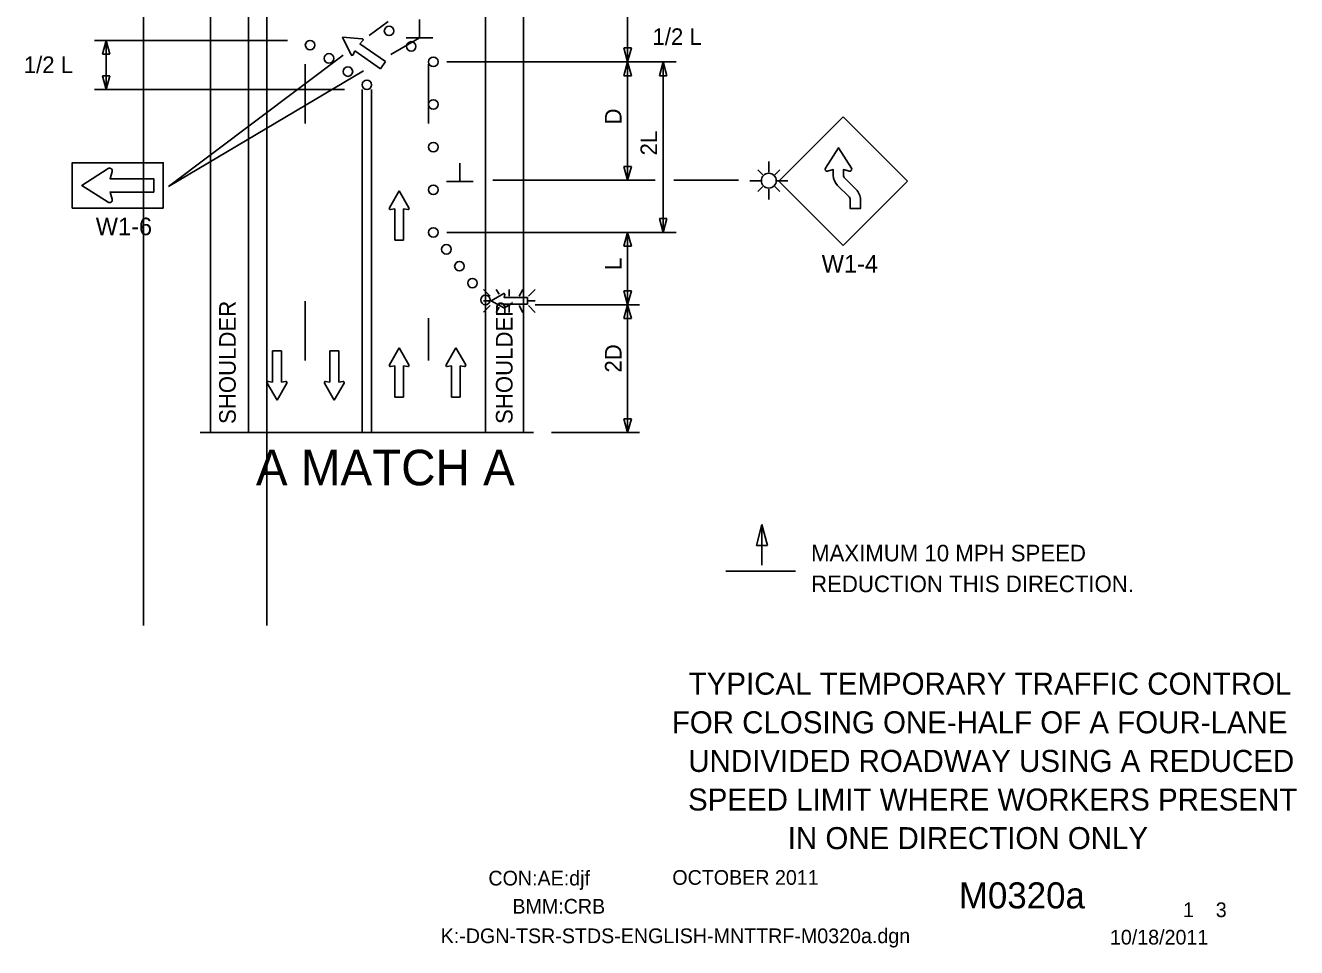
# Model space of a CAD drawing. Extents: x 16473 to 19504, y 4850 to 6923.
# Drawn here: x 16895 to 17432, y 5932 to 6321 of the extents above; entities that cross this region are included whole.
import ezdxf

# ---------------------------------------------------------------- set-up
doc = ezdxf.new("R2010")
doc.units = 0
for name, color, linetype in [('ALI_LEGAL_EX', 7, 'Continuous'), ('BORDER_SIGNAL_WO', 7, 'Continuous'), ('MT_SCRATCH_LEVEL_E', 7, 'Continuous'), ('PAVT_EDGE_EX', 7, 'Continuous'), ('TRAFFIC_SIGNS_PR', 7, 'Continuous'), ('TYPICAL_TEXT_DIMEN_PR', 7, 'Continuous')]:
    doc.layers.add(name, color=color, linetype=linetype)

msp = doc.modelspace()

# ---------------------------------------------------------------- linework, layer by layer
at = {"layer": 'ALI_LEGAL_EX'}
for p, q in [((16945.19, 6918.86), (16945.19, 6067.75)), ((16997.19, 6918.86), (16997.19, 6067.75))]:
    msp.add_line(p, q, dxfattribs=at)
for points in [[(17013.43, 6304.69), (17013.43, 6279.69)], [(17065.43, 6304.69), (17065.43, 6279.69)], [(17013.43, 6204.69), (17013.43, 6179.69)], [(17065.43, 6197.47), (17065.43, 6179.69)]]:
    msp.add_lwpolyline(points, dxfattribs=at)
at = {"layer": 'MT_SCRATCH_LEVEL_E'}
for p, q in [((17029.15, 6316.2), (17032.73, 6308.68)), ((17037.46, 6315.45), (17029.15, 6316.2)), ((17029.15, 6316.2), (17032.73, 6308.68)), ((17037.46, 6315.45), (17029.15, 6316.2)), ((17036.47, 6313.39), (17037.74, 6314.67)), ((17036.47, 6313.39), (17037.74, 6314.67)), ((17047.34, 6305.8), (17036.47, 6313.39)), ((17047.34, 6305.8), (17036.47, 6313.39)), ((17033.57, 6308.69), (17034.33, 6310.33)), ((17033.57, 6308.69), (17034.33, 6310.33)), ((17034.33, 6310.33), (17045.19, 6302.73)), ((17034.33, 6310.33), (17045.19, 6302.73)), ((17045.19, 6302.73), (17047.34, 6305.8)), ((17045.19, 6302.73), (17047.34, 6305.8)), ((17053.03, 6251.28), (17048.92, 6244.04)), ((17053.03, 6251.28), (17048.92, 6244.04)), ((17057.17, 6244.04), (17053.03, 6251.28)), ((17057.17, 6244.04), (17053.03, 6251.28)), ((17049.4, 6243.36), (17051.17, 6243.67)), ((17049.4, 6243.36), (17051.17, 6243.67)), ((17051.17, 6243.67), (17051.17, 6230.42)), ((17051.17, 6243.67), (17051.17, 6230.42)), ((17054.92, 6230.42), (17054.92, 6243.67)), ((17054.92, 6243.67), (17056.69, 6243.36)), ((17054.92, 6230.42), (17054.92, 6243.67)), ((17054.92, 6243.67), (17056.69, 6243.36)), ((17051.17, 6230.42), (17054.92, 6230.42)), ((17051.17, 6230.42), (17054.92, 6230.42)), ((17053.03, 6185.06), (17048.92, 6177.82)), ((17053.03, 6185.06), (17048.92, 6177.82)), ((17057.17, 6177.82), (17053.03, 6185.06)), ((17057.17, 6177.82), (17053.03, 6185.06)), ((17076.95, 6185.06), (17072.84, 6177.82)), ((17076.95, 6185.06), (17072.84, 6177.82)), ((17081.1, 6177.82), (17076.95, 6185.06)), ((17081.1, 6177.82), (17076.95, 6185.06)), ((17003.35, 6183.78), (16999.61, 6183.78)), ((16999.61, 6183.78), (16999.61, 6170.52)), ((17003.35, 6183.78), (16999.61, 6183.78)), ((16999.61, 6183.78), (16999.61, 6170.52)), ((17003.35, 6170.52), (17003.35, 6183.78)), ((17003.35, 6170.52), (17003.35, 6183.78)), ((17027.53, 6183.78), (17023.79, 6183.78)), ((17023.79, 6183.78), (17023.79, 6170.52)), ((17027.53, 6183.78), (17023.79, 6183.78)), ((17023.79, 6183.78), (17023.79, 6170.52)), ((17027.53, 6170.52), (17027.53, 6183.78)), ((17027.53, 6170.52), (17027.53, 6183.78)), ((17049.4, 6177.14), (17051.17, 6177.45)), ((17049.4, 6177.14), (17051.17, 6177.45)), ((17051.17, 6177.45), (17051.17, 6164.2)), ((17051.17, 6177.45), (17051.17, 6164.2)), ((17054.92, 6164.2), (17054.92, 6177.45)), ((17054.92, 6177.45), (17056.69, 6177.14)), ((17054.92, 6164.2), (17054.92, 6177.45)), ((17054.92, 6177.45), (17056.69, 6177.14)), ((17073.32, 6177.14), (17075.1, 6177.45)), ((17073.32, 6177.14), (17075.1, 6177.45)), ((17075.1, 6177.45), (17075.1, 6164.2)), ((17075.1, 6177.45), (17075.1, 6164.2)), ((17078.84, 6164.2), (17078.84, 6177.45)), ((17078.84, 6177.45), (17080.62, 6177.14)), ((17078.84, 6164.2), (17078.84, 6177.45)), ((17078.84, 6177.45), (17080.62, 6177.14)), ((16997.35, 6170.15), (17001.5, 6162.91)), ((16997.35, 6170.15), (17001.5, 6162.91)), ((16999.61, 6170.52), (16997.83, 6170.84)), ((16999.61, 6170.52), (16997.83, 6170.84)), ((17001.5, 6162.91), (17005.61, 6170.15)), ((17001.5, 6162.91), (17005.61, 6170.15)), ((17005.13, 6170.84), (17003.35, 6170.52)), ((17005.13, 6170.84), (17003.35, 6170.52)), ((17021.53, 6170.15), (17025.68, 6162.91)), ((17021.53, 6170.15), (17025.68, 6162.91)), ((17023.79, 6170.52), (17022.01, 6170.84)), ((17023.79, 6170.52), (17022.01, 6170.84)), ((17025.68, 6162.91), (17029.79, 6170.15)), ((17025.68, 6162.91), (17029.79, 6170.15)), ((17029.31, 6170.84), (17027.53, 6170.52)), ((17029.31, 6170.84), (17027.53, 6170.52)), ((17051.17, 6164.2), (17054.92, 6164.2)), ((17051.17, 6164.2), (17054.92, 6164.2)), ((17075.1, 6164.2), (17078.84, 6164.2)), ((17075.1, 6164.2), (17078.84, 6164.2))]:
    msp.add_line(p, q, dxfattribs=at)
for centre, start, end in [((17037.41, 6314.99), 315.105, 84.8419), ((17037.41, 6314.99), 315.105, 84.8419), ((17033.15, 6308.89), 205.4936, 335.0326), ((17033.15, 6308.89), 205.4936, 335.0326), ((17049.32, 6243.82), 150.4248, 279.9638), ((17049.32, 6243.82), 150.4248, 279.9638), ((17056.76, 6243.82), 260.0362, 29.7731), ((17056.76, 6243.82), 260.0362, 29.7731), ((17049.32, 6177.6), 150.4248, 279.9638), ((17049.32, 6177.6), 150.4248, 279.9638), ((17056.76, 6177.6), 260.0362, 29.7731), ((17056.76, 6177.6), 260.0362, 29.7731), ((17073.25, 6177.6), 150.4248, 279.9638), ((17073.25, 6177.6), 150.4248, 279.9638), ((17080.69, 6177.6), 260.0362, 29.7731), ((17080.69, 6177.6), 260.0362, 29.7731), ((16997.76, 6170.37), 80.0362, 209.7731), ((16997.76, 6170.37), 80.0362, 209.7731), ((17005.2, 6170.38), 330.4248, 99.9638), ((17005.2, 6170.38), 330.4248, 99.9638), ((17021.94, 6170.37), 80.0362, 209.7731), ((17021.94, 6170.37), 80.0362, 209.7731), ((17029.38, 6170.38), 330.4248, 99.9638), ((17029.38, 6170.38), 330.4248, 99.9638)]:
    msp.add_arc(centre, 0.463, start, end, dxfattribs=at)
at = {"layer": 'PAVT_EDGE_EX'}
for p, q in [((16973.43, 6873.99), (16973.43, 6149.2)), ((16989.43, 6873.99), (16989.43, 6149.2)), ((17089.43, 6873.99), (17089.43, 6149.2)), ((17105.43, 6873.99), (17105.43, 6149.2)), ((17037.43, 6294.02), (17037.43, 6149.2)), ((17041.43, 6294.02), (17041.43, 6149.2))]:
    msp.add_line(p, q, dxfattribs=at)
at = {"layer": 'TRAFFIC_SIGNS_PR'}
for p, q in [((17213.17, 6255.35), (17240.32, 6282.5)), ((17267.47, 6255.35), (17240.32, 6282.5)), ((16930.24, 6260.66), (16919.08, 6253.56)), ((16931.08, 6256.36), (16931.92, 6259.42)), ((17206.49, 6258.07), (17204.38, 6260.18)), ((17209, 6259.11), (17209, 6263.61)), ((17211.51, 6258.07), (17213.62, 6260.18)), ((16949.48, 6256.36), (16931.08, 6256.36)), ((16949.48, 6256.36), (16949.48, 6250.76)), ((17205.84, 6255.56), (17201.01, 6255.56)), ((17212.15, 6255.56), (17217.03, 6255.56)), ((17240.32, 6228.2), (17213.17, 6255.35)), ((17267.47, 6255.35), (17240.32, 6228.2)), ((17245.79, 6251.88), (17241.08, 6256.6)), ((17241.08, 6256.6), (17245.79, 6251.88)), ((16919.08, 6253.56), (16930.24, 6246.46)), ((16931.92, 6247.7), (16931.08, 6250.76)), ((16931.08, 6250.76), (16949.48, 6250.76)), ((17206.48, 6253.04), (17204.38, 6250.94)), ((17209, 6247.59), (17209, 6252)), ((17211.51, 6253.04), (17213.62, 6250.94)), ((17242.74, 6248.83), (17238.03, 6253.55)), ((17242.74, 6248.83), (17238.03, 6253.55)), ((17088.56, 6209.69), (17091.38, 6206.87)), ((17094, 6209.69), (17095.21, 6207.59)), ((17099.47, 6206.87), (17099.47, 6209.69)), ((17105.26, 6209.69), (17103.63, 6206.87)), ((17107.55, 6206.87), (17110.37, 6209.69)), ((17091.38, 6204.84), (17088.56, 6204.84)), ((17088.56, 6199.99), (17091.38, 6202.8)), ((17095.28, 6202.17), (17094.02, 6199.98)), ((17099.47, 6202.8), (17099.47, 6199.98)), ((17103.6, 6202.8), (17105.23, 6199.98)), ((17107.55, 6204.84), (17110.37, 6204.84)), ((17107.55, 6202.8), (17110.37, 6199.98))]:
    msp.add_line(p, q, dxfattribs=at)
for points in [[(17232.87, 6260.87), (17238.36, 6269.48), (17243.84, 6260.87)], [(17232.87, 6260.87), (17238.36, 6269.48), (17243.84, 6260.87)], [(16930.24, 6246.46), (16919.08, 6253.56), (16930.24, 6260.66)], [(16931.92, 6259.42), (16931.08, 6256.36), (16949.48, 6256.36), (16949.48, 6250.76), (16931.08, 6250.76), (16931.92, 6247.7)], [(17236.2, 6257.86), (17236.2, 6260.22), (17233.83, 6259.58)], [(17236.2, 6257.86), (17236.2, 6260.22), (17233.83, 6259.58)], [(17242.88, 6259.58), (17240.51, 6260.22), (17240.52, 6257.93)], [(17242.88, 6259.57), (17242.04, 6259.8), (17240.51, 6260.22), (17240.52, 6257.93)], [(17247.66, 6247.46), (17247.66, 6243.76), (17243.34, 6243.76), (17243.34, 6247.46)], [(17097.14, 6201.82), (17091.83, 6204.84), (17097.14, 6207.88)], [(17097.64, 6207.52), (17097.41, 6206.22), (17107.13, 6206.22), (17107.13, 6203.48), (17097.41, 6203.48), (17097.64, 6202.17)]]:
    msp.add_lwpolyline(points, dxfattribs=at)
msp.add_lwpolyline([(16953.48, 6243.96), (16915.08, 6243.96), (16915.08, 6263.16), (16953.48, 6263.16)], close=True, dxfattribs=at)
for centre, radius in [((17048.77, 6318.77), 2), ((17015.43, 6312.78), 2), ((17058.11, 6312.24), 2), ((17023.43, 6307.19), 2), ((17067.46, 6305.72), 2), ((17031.43, 6301.6), 2), ((17039.43, 6296.02), 2), ((17067.46, 6287.72), 2), ((17067.46, 6269.72), 2), ((17067.46, 6251.72), 2), ((17209, 6255.56), 3.15), ((17067.46, 6233.72), 2), ((17072.95, 6226.58), 2), ((17078.45, 6219.46), 2), ((17083.95, 6212.33), 2), ((17089.44, 6205.2), 2)]:
    msp.add_circle(centre, radius, dxfattribs=at)
for centre, radius, start, end in [((16930.84, 6259.72), 1.12, 344.6731, 122.4696), ((16930.84, 6259.72), 1.12, 344.6731, 122.4696), ((17233.6, 6260.41), 0.866, 147.7292, 285.3172), ((17233.61, 6260.41), 0.866, 147.7196, 285.3201), ((17223.76, 6266.67), 10.8, 327.5335, 327.5431), ((17236.69, 6249.16), 10.8, 105.3192, 105.32), ((17243.11, 6260.41), 0.866, 254.6148, 32.4712), ((17242.37, 6257.92), 6.17, 180.6181, 225.7875), ((17242.37, 6257.93), 6.17, 180.6245, 225.2313), ((17242.37, 6257.93), 1.85, 179.8762, 225.7877), ((17242.37, 6257.92), 1.85, 180, 225.7875), ((17241.49, 6247.46), 1.85, 0, 47.628), ((17241.49, 6247.46), 6.17, 0, 45.7883), ((16930.84, 6247.4), 1.12, 237.5304, 15.3269), ((16930.84, 6247.4), 1.12, 237.5304, 15.3269), ((17097.3, 6207.58), 0.341, 350.0407, 118.5167), ((17097.31, 6202.12), 0.341, 241.1084, 9.2692)]:
    msp.add_arc(centre, radius, start, end, dxfattribs=at)
at = {"layer": 'TYPICAL_TEXT_DIMEN_PR'}
for p, q in [((17061.59, 6315.87), (17061.59, 6323.65)), ((17149.43, 6327.29), (17149.43, 6305.72)), ((17040.39, 6316.77), (17048.33, 6322.74)), ((16924.43, 6314.78), (17005.97, 6314.78)), ((16927.86, 6308.91), (16929.43, 6314.78)), ((16929.43, 6294.02), (16929.43, 6314.78)), ((16929.43, 6314.78), (16931, 6308.91)), ((17061.59, 6315.87), (17049.59, 6308.76)), ((17067.21, 6315.87), (17055.96, 6315.87)), ((16929.43, 6308.91), (16927.86, 6308.91)), ((16931, 6308.91), (16929.43, 6308.91)), ((16955.69, 6253.16), (17029.36, 6308.49)), ((17149.43, 6305.72), (17147.86, 6311.58)), ((17147.86, 6311.58), (17149.43, 6311.58)), ((17149.43, 6311.58), (17151, 6311.58)), ((17151, 6311.58), (17149.43, 6305.72)), ((17154.43, 6305.72), (17073.2, 6305.72)), ((17154.43, 6305.72), (17073.2, 6305.72)), ((17169.86, 6305.72), (17073.2, 6305.72)), ((17147.86, 6299.86), (17149.43, 6305.72)), ((17149.43, 6255.72), (17149.43, 6305.72)), ((17149.43, 6305.72), (17151, 6299.86)), ((17162.86, 6299.86), (17164.43, 6305.72)), ((17164.43, 6233.72), (17164.43, 6305.72)), ((17164.43, 6305.72), (17166, 6299.86)), ((16929.43, 6294.02), (16927.86, 6299.88)), ((16927.86, 6299.88), (16929.43, 6299.88)), ((16929.43, 6299.88), (16931, 6299.88)), ((16931, 6299.88), (16929.43, 6294.02)), ((17037.99, 6301.89), (16955.69, 6253.16)), ((17149.43, 6299.86), (17147.86, 6299.86)), ((17151, 6299.86), (17149.43, 6299.86)), ((17164.43, 6299.86), (17162.86, 6299.86)), ((17166, 6299.86), (17164.43, 6299.86)), ((16924.43, 6294.02), (17029.97, 6294.02)), ((17078.59, 6255.17), (17078.59, 6262.96)), ((17149.43, 6255.72), (17147.86, 6261.58)), ((17147.86, 6261.58), (17149.43, 6261.58)), ((17149.43, 6261.58), (17151, 6261.58)), ((17151, 6261.58), (17149.43, 6255.72)), ((17084.22, 6255.17), (17072.97, 6255.17)), ((17161.07, 6255.72), (17092.61, 6255.72)), ((17196.26, 6255.72), (17168.98, 6255.72)), ((17164.43, 6233.72), (17162.86, 6239.58)), ((17162.86, 6239.58), (17164.43, 6239.58)), ((17164.43, 6239.58), (17166, 6239.58)), ((17166, 6239.58), (17164.43, 6233.72)), ((17169.86, 6233.72), (17073.2, 6233.72)), ((17147.86, 6227.85), (17149.43, 6233.72)), ((17149.43, 6203.2), (17149.43, 6233.72)), ((17149.43, 6233.72), (17151, 6227.85)), ((17149.43, 6227.85), (17147.86, 6227.85)), ((17151, 6227.85), (17149.43, 6227.85)), ((17149.43, 6203.2), (17147.86, 6209.07)), ((17147.86, 6209.07), (17149.43, 6209.07)), ((17149.43, 6209.07), (17151, 6209.07)), ((17151, 6209.07), (17149.43, 6203.2)), ((17154.43, 6203.2), (17110.45, 6203.2)), ((17147.86, 6197.34), (17149.43, 6203.2)), ((17149.43, 6203.2), (17149.43, 6149.2)), ((17149.43, 6203.2), (17151, 6197.34)), ((17149.43, 6197.34), (17147.86, 6197.34)), ((17151, 6197.34), (17149.43, 6197.34)), ((17149.43, 6149.2), (17147.86, 6155.07)), ((17147.86, 6155.07), (17149.43, 6155.07)), ((17149.43, 6155.07), (17151, 6155.07)), ((17151, 6155.07), (17149.43, 6149.2)), ((16969.13, 6149.2), (17109.73, 6149.2)), ((17154.43, 6149.2), (17117.3, 6149.2)), ((17203.76, 6101.57), (17206.12, 6110.36)), ((17206.12, 6093.23), (17206.12, 6110.36)), ((17206.12, 6110.36), (17208.47, 6101.57)), ((17206.12, 6101.57), (17203.76, 6101.57)), ((17208.47, 6101.57), (17206.12, 6101.57)), ((17220.29, 6090.73), (17190.85, 6090.73))]:
    msp.add_line(p, q, dxfattribs=at)

# ---------------------------------------------------------------- texts
at = {"layer": 'BORDER_SIGNAL_WO'}
for s, height, p in [('TYPICAL TEMPORARY TRAFFIC CONTROL', 9.3, (17175.21, 6038.59)), ('FOR CLOSING ONE-HALF OF A FOUR-LANE', 9.3, (17168.06, 6022.29)), ('UNDIVIDED ROADWAY USING A REDUCED', 9.3, (17175.02, 6005.99)), ('SPEED LIMIT WHERE WORKERS PRESENT', 9.3, (17174.92, 5989.69)), ('IN ONE DIRECTION ONLY', 9.3, (17216.99, 5973.39)), ('CON:AE:djf', 6.2, (17090.69, 5958.06)), ('    OCTOBER 2011    ', 6.2, (17159.08, 5958.34)), ('    M0320a   ', 11, (17272.86, 5948.38)), ('BMM:CRB   ', 6.2, (17100.81, 5946.17)), (' 1    3 ', 6.2, (17381.45, 5944.7)), ('K:-DGN-TSR-STDS-ENGLISH-MNTTRF-M0320a.dgn        ', 6.2, (17070.55, 5933.71)), ('10/18/2011    ', 6.2, (17352.93, 5933.13))]:
    msp.add_text(s, height=height, dxfattribs=at).set_placement(p)
at = {"layer": 'TRAFFIC_SIGNS_PR'}
for s, p in [('W1-6', (16925.02, 6232.52)), ('W1-4', (17231.32, 6216.76))]:
    msp.add_text(s, height=7.44, dxfattribs=at).set_placement(p)
at = {"layer": 'TYPICAL_TEXT_DIMEN_PR'}
for s, height, p in [('1/2 L', 7, (17159.9, 6312.85)), ('1/2 L', 7, (16894.63, 6300.99)), ('A MATCH A', 15, (16992.6, 6126.96)), ('MAXIMUM 10 MPH SPEED', 7, (17226.83, 6094.87)), ('REDUCTION THIS DIRECTION.', 7, (17226.83, 6081.87))]:
    msp.add_text(s, height=height, dxfattribs=at).set_placement(p)
for s, p in [('D', (17146.87, 6279.27)), ('2L', (17161.87, 6266.22)), ('L', (17146.87, 6217.82)), ('SHOULDER', (16984.08, 6152.85)), ('SHOULDER', (17100.87, 6152.87)), ('2D', (17146.87, 6174.55))]:
    msp.add_text(s, height=7, rotation=90, dxfattribs=at).set_placement(p)

doc.saveas('drawing.dxf')
